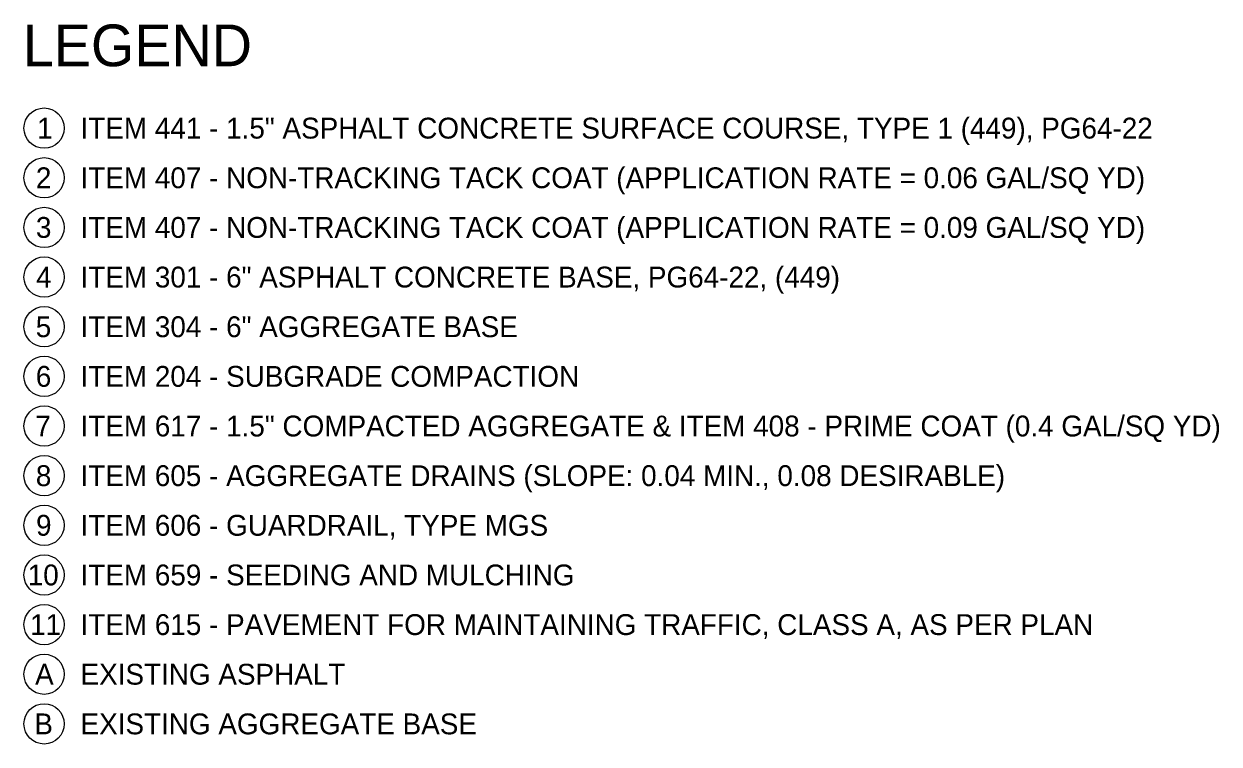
# Model space of a CAD drawing. Extents: x -345 to 102, y -108 to 100.
# Drawn here: x -57.28 to -33.19, y -66.5 to -52 of the extents above; entities that cross this region are included whole.
import ezdxf

# ---------------------------------------------------------------- set-up
doc = ezdxf.new("R2010")
doc.units = 0
doc.layers.add('SH_Text', color=7, linetype='Continuous')
doc.layers.add('TX_P_1', color=7, linetype='Continuous')

msp = doc.modelspace()

# ---------------------------------------------------------------- linework, layer by layer
at = {"layer": 'TX_P_1'}
for centre in [(-56.875, -54.097), (-56.875, -55.097), (-56.875, -56.097), (-56.875, -57.097), (-56.875, -58.097), (-56.875, -59.097), (-56.875, -60.097), (-56.875, -61.097), (-56.875, -62.097), (-56.875, -63.097), (-56.875, -64.097), (-56.875, -65.097), (-56.875, -66.097)]:
    msp.add_circle(centre, 0.406, dxfattribs=at)

# ---------------------------------------------------------------- texts
at = {"layer": 'SH_Text'}
msp.add_text('LEGEND', height=0.84, dxfattribs=at).set_placement((-57.304, -52.85))
at = {"layer": 'TX_P_1'}
for s, p in [('1', (-57.016, -54.307)), ('ITEM 441 - 1.5" ASPHALT CONCRETE SURFACE COURSE, TYPE 1 (449), PG64-22', (-56.14, -54.307)), ('2', (-57.04, -55.307)), ('ITEM 407 - NON-TRACKING TACK COAT (APPLICATION RATE = 0.06 GAL/SQ YD)', (-56.14, -55.307)), ('3', (-57.039, -56.307)), ('ITEM 407 - NON-TRACKING TACK COAT (APPLICATION RATE = 0.09 GAL/SQ YD)', (-56.14, -56.307)), ('4', (-57.035, -57.307)), ('ITEM 301 - 6" ASPHALT CONCRETE BASE, PG64-22, (449)', (-56.14, -57.307)), ('5', (-57.043, -58.307)), ('ITEM 304 - 6" AGGREGATE BASE', (-56.14, -58.307)), ('6', (-57.042, -59.307)), ('ITEM 204 - SUBGRADE COMPACTION', (-56.14, -59.307)), ('7', (-57.05, -60.307)), ('ITEM 617 - 1.5" COMPACTED AGGREGATE & ITEM 408 - PRIME COAT (0.4 GAL/SQ YD)', (-56.14, -60.307)), ('8', (-57.041, -61.307)), ('ITEM 605 - AGGREGATE DRAINS (SLOPE: 0.04 MIN., 0.08 DESIRABLE)', (-56.14, -61.307)), ('9', (-57.037, -62.307)), ('ITEM 606 - GUARDRAIL, TYPE MGS', (-56.14, -62.307)), ('10', (-57.204, -63.307)), ('ITEM 659 - SEEDING AND MULCHING', (-56.14, -63.307)), ('11', (-57.157, -64.307)), ('ITEM 615 - PAVEMENT FOR MAINTAINING TRAFFIC, CLASS A, AS PER PLAN', (-56.14, -64.307)), ('A', (-57.056, -65.307)), ('EXISTING ASPHALT', (-56.14, -65.307)), ('B', (-57.071, -66.307)), ('EXISTING AGGREGATE BASE', (-56.14, -66.307))]:
    msp.add_text(s, height=0.42, dxfattribs=at).set_placement(p)

doc.saveas('drawing.dxf')
